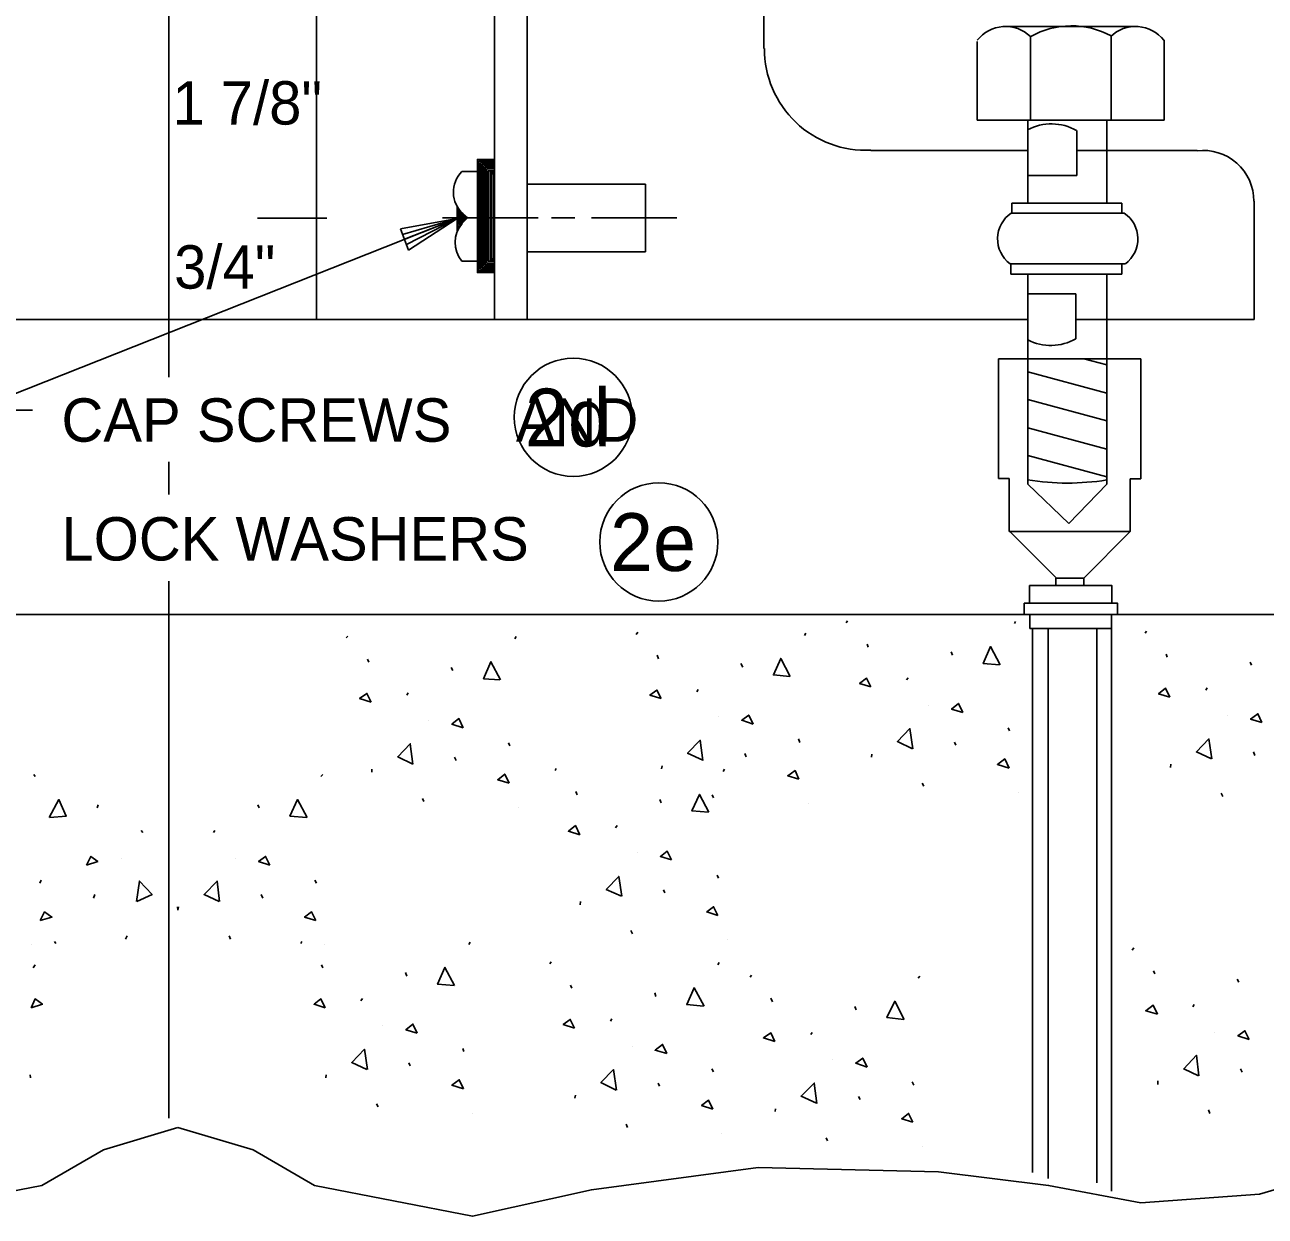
# Model space of a CAD drawing. Extents: x 12.3 to 19.6, y 18.8 to 29.6.
# Drawn here: x 15.033 to 16.749, y 21.66 to 23.308 of the extents above; entities that cross this region are included whole.
import ezdxf

# ---------------------------------------------------------------- set-up
doc = ezdxf.new("R2010")
doc.units = 0
for name, color, linetype in [('BORD-LINE', 7, 'Continuous'), ('DETL-DIMS', 7, 'Continuous'), ('DETL-LINE', 7, 'Continuous'), ('DETL-PATT', 7, 'Continuous')]:
    doc.layers.add(name, color=color, linetype=linetype)

msp = doc.modelspace()

# ---------------------------------------------------------------- linework, layer by layer
at = {"layer": 'BORD-LINE'}
for centre in [(15.7919, 22.765), (15.9102, 22.5926)]:
    msp.add_circle(centre, 0.0817, dxfattribs=at)
at = {"layer": 'DETL-DIMS'}
for p, q in [((15.2325, 25.0229), (15.2325, 22.8206)), ((15.4368, 24.068), (15.4368, 22.9003)), ((15.4511, 23.0403), (15.3552, 23.0403)), ((15.5527, 23.0256), (15.6312, 23.04)), ((15.6312, 23.04), (15.5557, 23.0178)), ((15.5586, 23.0112), (15.6312, 23.04)), ((15.6312, 23.04), (15.5611, 23.0041)), ((15.5641, 22.9963), (15.6312, 23.04)), ((15.6108, 23.0406), (15.7432, 23.0406)), ((15.7619, 23.0406), (15.7942, 23.0406)), ((15.817, 23.0406), (15.935, 23.0406)), ((15.5641, 22.9963), (15.5527, 23.0256)), ((15.2325, 22.7032), (15.2325, 22.658)), ((15.2325, 22.5383), (15.2325, 21.7957))]:
    msp.add_line(p, q, dxfattribs=at)
for points in [[(14.9616, 22.775), (15.6312, 23.04)], [(15.0437, 22.775), (14.9616, 22.775), (14.8549, 22.9843)]]:
    msp.add_lwpolyline(points, dxfattribs=at)
at = {"layer": 'DETL-LINE'}
for p, q in [((15.6827, 24.5643), (15.6827, 22.9003)), ((15.7282, 24.5542), (15.7282, 22.9003)), ((16.0556, 23.555), (16.0556, 23.275)), ((16.3864, 23.3055), (16.5704, 23.3055)), ((16.3505, 23.1761), (16.3505, 23.2846)), ((16.4242, 23.1761), (16.4242, 23.2912)), ((16.5357, 23.1761), (16.5357, 23.293)), ((16.6094, 23.1761), (16.6094, 23.2864)), ((16.3505, 23.1761), (16.6094, 23.1761)), ((16.4206, 23.061), (16.4206, 23.1761)), ((16.4769, 23.1761), (16.4769, 23.1755)), ((16.5297, 23.061), (16.5297, 23.1761)), ((16.4883, 23.1617), (16.4883, 23.0994)), ((16.4206, 23.1341), (16.2036, 23.1341)), ((16.655, 23.1341), (16.4883, 23.1341)), ((16.4883, 23.0994), (16.4206, 23.0994)), ((15.8919, 23.0874), (15.7282, 23.0874)), ((15.8919, 23.0874), (15.8919, 22.9938)), ((16.3984, 23.0472), (16.3984, 23.061)), ((16.5507, 23.0472), (16.5507, 23.061)), ((16.7335, 22.9003), (16.7335, 23.064)), ((15.6312, 23.0208), (15.6312, 23.0568)), ((15.645, 23.04), (15.6312, 23.0538)), ((15.6443, 23.0395), (15.6312, 23.052)), ((15.6437, 23.0388), (15.6312, 23.049)), ((15.6426, 23.0376), (15.6312, 23.0466)), ((15.6413, 23.0365), (15.6312, 23.0442)), ((15.6456, 23.0406), (15.6396, 23.046)), ((15.6402, 23.0352), (15.6312, 23.0418)), ((15.639, 23.034), (15.6312, 23.04)), ((15.6377, 23.0328), (15.6312, 23.0376)), ((15.6366, 23.0316), (15.6312, 23.0358)), ((15.636, 23.0298), (15.6312, 23.034)), ((15.6347, 23.0286), (15.6312, 23.0316)), ((15.6342, 23.0275), (15.6312, 23.0298)), ((15.6336, 23.0262), (15.6312, 23.0281)), ((15.633, 23.0251), (15.6312, 23.0268)), ((15.6456, 23.0406), (15.6377, 23.0328)), ((15.6323, 23.0245), (15.6312, 23.0256)), ((15.6317, 23.0232), (15.6312, 23.0245)), ((15.6312, 23.0221), (15.6312, 23.0226)), ((15.8919, 22.9938), (15.7282, 22.9938)), ((16.3973, 22.9771), (16.3973, 22.9627)), ((16.5507, 22.9771), (16.5507, 22.9627)), ((16.4206, 22.8458), (16.4206, 22.9627)), ((16.5297, 22.8458), (16.5297, 22.9627)), ((16.4872, 22.9357), (16.4206, 22.9357)), ((16.4872, 22.8734), (16.4872, 22.9357)), ((15.7282, 22.9112), (15.7282, 22.9052)), ((16.4206, 22.9003), (14.0703, 22.9003)), ((16.7335, 22.9003), (16.4872, 22.9003)), ((16.5771, 22.8458), (16.3799, 22.8458)), ((16.3799, 22.8458), (16.3799, 22.6804)), ((16.4206, 22.6726), (16.4206, 22.8458)), ((16.5297, 22.8374), (16.4979, 22.8458)), ((16.5297, 22.6726), (16.5297, 22.8458)), ((16.5771, 22.8458), (16.5771, 22.6798)), ((16.5297, 22.7984), (16.4206, 22.8278)), ((16.5297, 22.7601), (16.4206, 22.7895)), ((16.5297, 22.7211), (16.4206, 22.7505)), ((16.5297, 22.6828), (16.4206, 22.7121)), ((16.3948, 22.6804), (16.3799, 22.6804)), ((16.3948, 22.6804), (16.3948, 22.6072)), ((16.4775, 22.618), (16.4206, 22.6726)), ((16.4775, 22.618), (16.5297, 22.6726)), ((16.5771, 22.6798), (16.5621, 22.6798)), ((16.5621, 22.6798), (16.5621, 22.6072)), ((16.4602, 22.5425), (16.3948, 22.6079)), ((16.5621, 22.6072), (16.3948, 22.6072)), ((16.4979, 22.5425), (16.5621, 22.6072)), ((16.4979, 22.5425), (16.4602, 22.5425)), ((14.0745, 22.4922), (15.2451, 22.4922)), ((16.4164, 22.4922), (15.2451, 22.4922)), ((15.8721, 22.4922), (15.8631, 22.4922)), ((15.9045, 22.4922), (15.9051, 22.4922)), ((16.5453, 22.4922), (16.5363, 22.4922)), ((16.5447, 22.4922), (17.2712, 22.4922)), ((16.4272, 22.473), (16.4272, 21.7207)), ((16.4488, 22.473), (16.4488, 21.7123)), ((16.5159, 22.473), (16.5159, 21.7063)), ((16.5363, 22.473), (16.5363, 21.6949))]:
    msp.add_line(p, q, dxfattribs=at)
for points in [[(15.6827, 23.1215), (15.6593, 23.1215), (15.6593, 22.9651), (15.6827, 22.9651)], [(15.6827, 23.1191), (15.6611, 23.1191), (15.6611, 22.9675), (15.6827, 22.9675)], [(15.6827, 23.1167), (15.6635, 23.1167), (15.6635, 22.9699), (15.6827, 22.9699)], [(15.6827, 23.115), (15.666, 23.115), (15.666, 22.9717), (15.6827, 22.9717)], [(15.6827, 23.1126), (15.6677, 23.1126), (15.6677, 22.9741), (15.6827, 22.9741)], [(15.6593, 23.1047), (15.6377, 23.1047)], [(15.6593, 23.1054), (15.6587, 23.1054)], [(15.6827, 23.1107), (15.6701, 23.1107), (15.6701, 22.9759), (15.6827, 22.9759)], [(15.6827, 23.1084), (15.672, 23.1084), (15.672, 22.9783), (15.6827, 22.9783)], [(15.6827, 23.106), (15.6743, 23.106), (15.6743, 22.9807), (15.6827, 22.9807)], [(15.6827, 23.1041), (15.6767, 23.1041), (15.6767, 22.9825), (15.6827, 22.9825)], [(15.6827, 23.1017), (15.6785, 23.1017), (15.6785, 22.9848), (15.6827, 22.9848)], [(15.6827, 23.1), (15.6809, 23.1), (15.6809, 22.9867), (15.6827, 22.9867)], [(16.5507, 23.061), (16.3984, 23.061)], [(16.5537, 23.0472), (16.3978, 23.0472)], [(15.6377, 22.9807), (15.6593, 22.9807)], [(16.396, 22.9771), (16.5554, 22.9771)], [(16.5507, 22.9627), (16.3973, 22.9627)], [(13.2197, 21.7633), (13.4337, 21.7453), (13.604, 21.7333), (13.7496, 21.6908), (13.9138, 21.6788), (14.0415, 21.7028), (14.1931, 21.7213), (14.4425, 21.7273), (14.6739, 21.6968), (14.8375, 21.6601), (15.0569, 21.7028), (15.1421, 21.7519), (15.2451, 21.783)], [(17.2712, 21.7633), (17.0572, 21.7453), (16.8869, 21.7333), (16.7413, 21.6908), (16.5771, 21.6788), (16.4494, 21.7028), (16.2971, 21.7213), (16.0478, 21.7273), (15.817, 21.6968), (15.6527, 21.6601), (15.4339, 21.7028), (15.3489, 21.7519), (15.2451, 21.783)]]:
    msp.add_lwpolyline(points, dxfattribs=at)
for points in [[(16.423, 22.5323), (16.5369, 22.5323), (16.5369, 22.5077), (16.423, 22.5077)], [(16.4979, 22.5425), (16.4595, 22.5425), (16.4595, 22.5323), (16.4979, 22.5323)], [(16.4158, 22.5077), (16.5447, 22.5077), (16.5447, 22.4922), (16.4158, 22.4922)], [(16.5363, 22.473), (16.4236, 22.473), (16.4236, 22.4922), (16.5363, 22.4922)]]:
    msp.add_lwpolyline(points, close=True, dxfattribs=at)
for centre, radius, start, end in [((16.3897, 23.2561), 0.0494, 45.7869, 142.2633), ((16.4811, 23.1915), 0.1148, 61.5487, 119.4363), ((16.5697, 23.2561), 0.0494, 37.7367, 134.2131), ((16.1965, 23.2744), 0.1402, 179.805, 272.8351), ((16.4533, 23.1007), 0.0701, 60.2386, 118.0159), ((16.6632, 23.064), 0.0701, 0, 96.9317), ((15.6663, 23.0764), 0.0403, 135.1028, 228.1706), ((16.4219, 23.0117), 0.0431, 124.132, 233.0361), ((16.5297, 23.0117), 0.0431, 306.9639, 55.868), ((15.6687, 23.007), 0.0403, 139.6417, 220.0725), ((16.4523, 22.9344), 0.0701, 242.9679, 299.7614), ((16.4756, 23.0185), 0.3445, 260.772, 279.0411)]:
    msp.add_arc(centre, radius, start, end, dxfattribs=at)
at = {"layer": 'DETL-PATT'}
for p, q in [((16.1712, 22.4837), (16.1695, 22.4808)), ((16.4038, 22.4826), (16.402, 22.4796)), ((15.4801, 22.4622), (15.4777, 22.4598)), ((15.7127, 22.4616), (15.7109, 22.4586)), ((15.8811, 22.4676), (15.8788, 22.4646)), ((16.1137, 22.4663), (16.1119, 22.4634)), ((16.5848, 22.4693), (16.5831, 22.4663)), ((16.2, 22.4472), (16.1982, 22.4514)), ((15.5089, 22.4262), (15.5071, 22.4304)), ((15.9099, 22.431), (15.9081, 22.4358)), ((16.3163, 22.4358), (16.3145, 22.4406)), ((16.6136, 22.4334), (16.6118, 22.4376)), ((16.7299, 22.4221), (16.7281, 22.4262)), ((15.6252, 22.4148), (15.6228, 22.4191)), ((16.0262, 22.4196), (16.0238, 22.4244)), ((16.2551, 22.4047), (16.2527, 22.4017)), ((15.5634, 22.3837), (15.5616, 22.3807)), ((15.9644, 22.3884), (15.9627, 22.3854)), ((16.6687, 22.3908), (16.667, 22.3878)), ((16.2827, 22.3669), (16.2827, 22.3669)), ((15.5916, 22.3459), (15.5916, 22.3459)), ((15.9926, 22.3507), (15.9926, 22.3507)), ((16.697, 22.3525), (16.697, 22.3525)), ((16.3954, 22.3315), (16.3936, 22.3357)), ((15.7043, 22.3105), (15.7025, 22.3147)), ((16.1053, 22.3153), (16.1035, 22.3202)), ((16.3211, 22.3117), (16.3193, 22.3159)), ((15.63, 22.2902), (15.6276, 22.2949)), ((16.0309, 22.2955), (16.0292, 22.2998)), ((16.2048, 22.2992), (16.2042, 22.2949)), ((16.7347, 22.2973), (16.7329, 22.3022)), ((15.0456, 22.271), (15.0473, 22.268)), ((15.4453, 22.271), (15.4429, 22.268)), ((15.5131, 22.2782), (15.5131, 22.274)), ((15.7684, 22.2794), (15.7666, 22.2764)), ((15.9147, 22.2829), (15.9141, 22.2788)), ((16.001, 22.2782), (15.9992, 22.2752)), ((16.6184, 22.2854), (16.6178, 22.2805)), ((16.2767, 22.2548), (16.2744, 22.259)), ((15.585, 22.2338), (15.5832, 22.238)), ((15.7972, 22.2428), (15.7954, 22.2476)), ((15.986, 22.2386), (15.9842, 22.2428)), ((16.4074, 22.2464), (16.4074, 22.2464)), ((16.6903, 22.2404), (16.688, 22.2452)), ((15.1331, 22.2248), (15.1348, 22.229)), ((15.3573, 22.2248), (15.3554, 22.229)), ((15.7157, 22.2254), (15.7157, 22.2254)), ((15.9135, 22.232), (15.9117, 22.2362)), ((16.1167, 22.2302), (16.1167, 22.2302)), ((15.1942, 22.1936), (15.1966, 22.1906)), ((15.2961, 22.1936), (15.2943, 22.1906)), ((15.8524, 22.2003), (15.8505, 22.1973)), ((15.1666, 22.1553), (15.1666, 22.1553)), ((15.3243, 22.1553), (15.3243, 22.1553)), ((15.8805, 22.1625), (15.8805, 22.1625)), ((15.0539, 22.1205), (15.0557, 22.1247)), ((15.4369, 22.1205), (15.4345, 22.1247)), ((15.9926, 22.1277), (15.9908, 22.1319)), ((15.1282, 22.1001), (15.1301, 22.1049)), ((15.3626, 22.1001), (15.3603, 22.1049)), ((15.9183, 22.1074), (15.9165, 22.1115)), ((15.2445, 22.0881), (15.2451, 22.0834)), ((15.2457, 22.0881), (15.2451, 22.0834)), ((15.802, 22.0954), (15.8014, 22.0905)), ((15.1726, 22.0432), (15.175, 22.048)), ((15.3176, 22.0432), (15.3159, 22.048)), ((15.8739, 22.0504), (15.8715, 22.0552)), ((15.0419, 22.0354), (15.0419, 22.0354)), ((15.0743, 22.0402), (15.0761, 22.0372)), ((15.4165, 22.0402), (15.4148, 22.0372)), ((15.4483, 22.0354), (15.4483, 22.0354)), ((15.6491, 22.039), (15.6473, 22.036)), ((16.0046, 22.0426), (16.0046, 22.0426)), ((16.5674, 22.0312), (16.5651, 22.0282)), ((15.0449, 22.0036), (15.0473, 22.0078)), ((15.4453, 22.0036), (15.4435, 22.0078)), ((15.5616, 21.9922), (15.5598, 21.9971)), ((15.7612, 22.012), (15.7595, 22.009)), ((15.9938, 22.0108), (15.992, 22.0078)), ((16.5962, 21.9952), (16.5944, 21.9995)), ((15.79, 21.9755), (15.7882, 21.9797)), ((16.0382, 21.9935), (16.0364, 21.9905)), ((16.2714, 21.9922), (16.269, 21.9892)), ((16.7125, 21.9838), (16.7101, 21.9881)), ((15.9063, 21.9641), (15.9045, 21.9688)), ((15.5005, 21.9611), (15.4981, 21.9581)), ((16.0676, 21.9568), (16.0652, 21.9617)), ((16.1832, 21.9455), (16.1815, 21.9503)), ((16.6508, 21.9527), (16.649, 21.9497)), ((15.8451, 21.9329), (15.8434, 21.9299)), ((15.5281, 21.9233), (15.5281, 21.9233)), ((16.1221, 21.9143), (16.1203, 21.9113)), ((16.679, 21.9143), (16.679, 21.9143)), ((15.8733, 21.8952), (15.8733, 21.8952)), ((15.6407, 21.8879), (15.639, 21.8922)), ((16.1502, 21.8766), (16.1502, 21.8766)), ((15.5664, 21.8682), (15.5646, 21.8723)), ((15.986, 21.8598), (15.9837, 21.8639)), ((16.7173, 21.8592), (16.7149, 21.8639)), ((15.0407, 21.8556), (15.0413, 21.8514)), ((15.4502, 21.8556), (15.4495, 21.8514)), ((15.9111, 21.84), (15.9093, 21.8442)), ((16.263, 21.8412), (16.2606, 21.8459)), ((16.6004, 21.8472), (16.6004, 21.8424)), ((15.7948, 21.8274), (15.7942, 21.8232)), ((16.1886, 21.8214), (16.1862, 21.8256)), ((15.5221, 21.8112), (15.5197, 21.8154)), ((16.0717, 21.8088), (16.0712, 21.8047)), ((15.6527, 21.8028), (15.6527, 21.8028)), ((16.6723, 21.8022), (16.6706, 21.807)), ((15.8668, 21.783), (15.8649, 21.7873)), ((15.9974, 21.7747), (15.9974, 21.7747)), ((16.1437, 21.7644), (16.1418, 21.7687)), ((16.2744, 21.756), (16.2744, 21.756))]:
    msp.add_line(p, q, dxfattribs=at)
for points in [[(16.3823, 22.4226), (16.369, 22.4478), (16.3589, 22.4244), (16.3816, 22.4226)], [(15.6911, 22.4017), (15.678, 22.4268), (15.6677, 22.4034), (15.6905, 22.4017)], [(16.0921, 22.4064), (16.0789, 22.4316), (16.0687, 22.4088), (16.0915, 22.4064)], [(16.2036, 22.3921), (16.1976, 22.4041), (16.188, 22.3968), (16.2036, 22.3921)], [(15.5124, 22.3711), (15.5065, 22.3831), (15.4963, 22.3759), (15.5124, 22.3711)], [(15.9135, 22.3759), (15.9075, 22.3878), (15.8979, 22.3807), (15.9135, 22.3759)], [(16.6172, 22.3777), (16.6112, 22.3903), (16.6016, 22.3824), (16.6172, 22.3777)], [(16.3307, 22.3567), (16.3247, 22.3693), (16.3151, 22.3614), (16.3307, 22.3567)], [(15.6396, 22.3357), (15.6336, 22.3483), (15.624, 22.3405), (15.6396, 22.3357)], [(16.0406, 22.3405), (16.0346, 22.3531), (16.0249, 22.3459), (16.0406, 22.3405)], [(16.7443, 22.3429), (16.7389, 22.3549), (16.7287, 22.3477), (16.7443, 22.3429)], [(16.2617, 22.3063), (16.2576, 22.3345), (16.2402, 22.3165), (16.2611, 22.3063)], [(15.5701, 22.2854), (15.5664, 22.3135), (15.5491, 22.2955), (15.5701, 22.2854)], [(15.971, 22.2902), (15.9674, 22.3183), (15.95, 22.3003), (15.971, 22.2908)], [(16.6753, 22.2925), (16.6712, 22.3202), (16.6538, 22.3022), (16.6747, 22.2925)], [(16.3948, 22.2799), (16.3888, 22.2925), (16.3786, 22.2848), (16.3948, 22.2799)], [(15.7031, 22.259), (15.6971, 22.2715), (15.6875, 22.2638), (15.7031, 22.259)], [(16.1041, 22.2644), (16.0987, 22.2764), (16.0886, 22.2692), (16.1041, 22.2644)], [(15.9794, 22.2188), (15.9663, 22.2434), (15.956, 22.2206), (15.9788, 22.2188)], [(15.0671, 22.2116), (15.0803, 22.2362), (15.0905, 22.2134), (15.0677, 22.2116)], [(15.4238, 22.2116), (15.4105, 22.2362), (15.3998, 22.2134), (15.4232, 22.2116)], [(15.8008, 22.1876), (15.7948, 22.2003), (15.7852, 22.1924), (15.8008, 22.1876)], [(15.1187, 22.1457), (15.1247, 22.1576), (15.1342, 22.1505), (15.1187, 22.1457)], [(15.3722, 22.1457), (15.3663, 22.1576), (15.3566, 22.1505), (15.3722, 22.1457)], [(15.9279, 22.1529), (15.9219, 22.1649), (15.9123, 22.1576), (15.9279, 22.1529)], [(15.1876, 22.0954), (15.1918, 22.1235), (15.2092, 22.1049), (15.1882, 22.0954)], [(15.3026, 22.0954), (15.2991, 22.1235), (15.2811, 22.1049), (15.3021, 22.0954)], [(15.8589, 22.1025), (15.8548, 22.1301), (15.8374, 22.1121), (15.8584, 22.1025)], [(15.992, 22.0761), (15.986, 22.0881), (15.9764, 22.081), (15.992, 22.0761)], [(15.0546, 22.069), (15.0605, 22.081), (15.0707, 22.0737), (15.0546, 22.069)], [(15.4358, 22.069), (15.4298, 22.081), (15.4202, 22.0737), (15.4358, 22.069)], [(15.6276, 21.9791), (15.6143, 22.0042), (15.6042, 21.9808), (15.627, 21.9791)], [(15.9728, 21.9508), (15.959, 21.9761), (15.9489, 21.9527), (15.9722, 21.9508)], [(15.0419, 21.9485), (15.0473, 21.9605), (15.0576, 21.9533), (15.0419, 21.9485)], [(15.4489, 21.9485), (15.4429, 21.9605), (15.4334, 21.9533), (15.4489, 21.9485)], [(16.2497, 21.9323), (16.2366, 21.9575), (16.2258, 21.9347), (16.2491, 21.9323)], [(16.5998, 21.9395), (16.5938, 21.9521), (16.5837, 21.9443), (16.5998, 21.9395)], [(15.7936, 21.9203), (15.7876, 21.9323), (15.778, 21.9251), (15.7936, 21.9203)], [(15.576, 21.9131), (15.5701, 21.9257), (15.5604, 21.9179), (15.576, 21.9131)], [(16.0706, 21.9017), (16.0652, 21.9137), (16.0549, 21.9066), (16.0706, 21.9017)], [(16.7269, 21.9047), (16.7209, 21.9167), (16.7113, 21.9096), (16.7269, 21.9047)], [(15.9213, 21.8849), (15.9153, 21.8976), (15.9051, 21.8897), (15.9213, 21.8849)], [(15.5071, 21.8628), (15.5029, 21.8909), (15.4855, 21.8729), (15.5065, 21.8628)], [(16.1982, 21.8663), (16.1922, 21.8789), (16.1826, 21.8718), (16.1982, 21.8663)], [(16.6573, 21.8544), (16.6538, 21.8826), (16.6364, 21.8639), (16.6568, 21.8544)], [(15.8518, 21.8346), (15.8475, 21.8628), (15.8301, 21.8448), (15.8511, 21.8346)], [(15.6402, 21.8364), (15.6342, 21.8489), (15.624, 21.8412), (15.6402, 21.8364)], [(16.1287, 21.816), (16.1251, 21.8442), (16.1071, 21.8262), (16.1281, 21.8166)], [(15.9848, 21.8082), (15.9788, 21.8208), (15.9693, 21.813), (15.9848, 21.8082)], [(16.2617, 21.7903), (16.2557, 21.8022), (16.2462, 21.795), (16.2617, 21.7903)]]:
    msp.add_lwpolyline(points, dxfattribs=at)

# ---------------------------------------------------------------- texts
at = {"layer": 'BORD-LINE'}
for s, height, p in [('1 7/8"', 0.06, (15.2374, 23.1698)), ('3/4"', 0.06, (15.2398, 22.9429)), ('2d', 0.0799, (15.725, 22.7247)), ('CAP SCREWS    AND', 0.06, (15.0839, 22.7312)), ('2e', 0.0799, (15.8428, 22.5524)), ('LOCK WASHERS', 0.06, (15.0839, 22.5669))]:
    msp.add_text(s, height=height, dxfattribs=at).set_placement(p)

doc.saveas('drawing.dxf')
